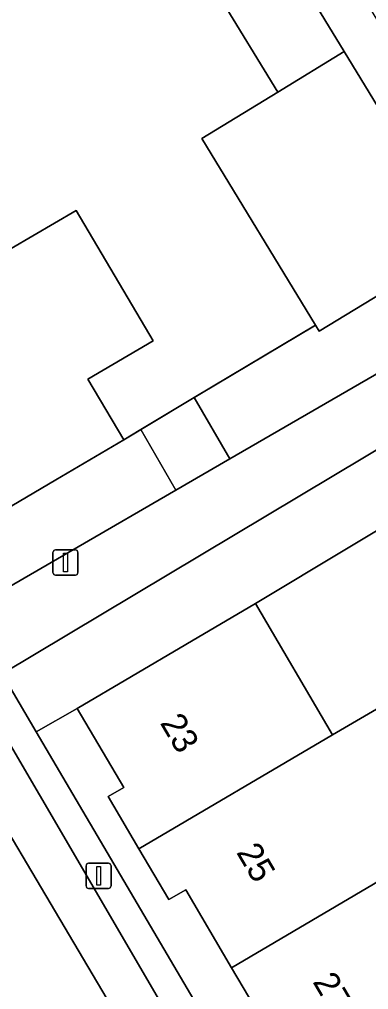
# Model space of a CAD drawing. Extents: x 159716 to 160783, y 383290 to 384031.
# Drawn here: x 160188.25 to 160202.09, y 383359.53 to 383397.98 of the extents above; entities that cross this region are included whole.
import ezdxf

# ---------------------------------------------------------------- set-up
doc = ezdxf.new("R2010")
doc.units = 0
for name, color, linetype in [('IMGEO_Erf', 7, 'Continuous'), ('IMGEO_Groenvoorziening', 7, 'Continuous'), ('IMGEO_Lichtmast', 7, 'Continuous'), ('IMGEO_Muur', 7, 'Continuous'), ('IMGEO_Pand', 7, 'Continuous'), ('IMGEO_Pand_nummerreeks', 7, 'Continuous'), ('IMGEO_Parkeervlak_open', 7, 'Continuous'), ('IMGEO_Rijbaan_lokaal_open', 7, 'Continuous'), ('IMGEO_Voetpad_open', 7, 'Continuous')]:
    doc.layers.add(name, color=color, linetype=linetype)

msp = doc.modelspace()

# ---------------------------------------------------------------- linework, layer by layer
at = {"layer": 'IMGEO_Erf'}
for points in [[(160181.914, 383399.101), (160184.914, 383394.006), (160187.924, 383388.895), (160190.508, 383390.403), (160193.555, 383385.244), (160190.972, 383383.719), (160192.386, 383381.318), (160193.063, 383381.722), (160195.185, 383382.99), (160199.992, 383385.86), (160195.482, 383393.257), (160198.495, 383395.094), (160196.187, 383398.879)], [(160227.095, 383381.23), (160221.425, 383377.618), (160221.195, 383377.966), (160215.218, 383374.346), (160210.282, 383382.434), (160208.629, 383381.443), (160197.607, 383374.829), (160200.666, 383369.63), (160202.72, 383370.829), (160204.837, 383372.065), (160205.907, 383370.232), (160204.528, 383369.427), (160206.435, 383366.161), (160206.78, 383366.365), (160208.731, 383363.025), (160210.088, 383363.872), (160211.199, 383362.093), (160206.673, 383359.423)], [(160198.463, 383357.343), (160196.666, 383360.397), (160194.844, 383363.493), (160194.175, 383363.099), (160192.992, 383365.109), (160191.774, 383367.179), (160192.387, 383367.54), (160190.544, 383370.673), (160188.923, 383369.749), (160213.993, 383327.146)]]:
    msp.add_lwpolyline(points, dxfattribs=at)
at = {"layer": 'IMGEO_Groenvoorziening'}
for points in [[(160200.487, 383401.152), (160200.376, 383401.334), (160198.823, 383400.487), (160201.131, 383396.702), (160205.789, 383389.062), (160207.21, 383386.705), (160208.76, 383387.602)], [(160207.21, 383386.705), (160205.789, 383389.062), (160200.14, 383385.618), (160199.992, 383385.86), (160195.185, 383382.99), (160196.592, 383380.559)], [(160208.629, 383381.443), (160207.249, 383383.817), (160187.571, 383372.047), (160188.923, 383369.749), (160190.544, 383370.673), (160194.854, 383373.209), (160197.607, 383374.829)], [(160193.788, 383378.936), (160194.453, 383379.321), (160193.063, 383381.722), (160192.386, 383381.318), (160189.694, 383379.733), (160185.385, 383377.195), (160184.751, 383376.839), (160186.126, 383374.501)]]:
    msp.add_lwpolyline(points, close=True, dxfattribs=at)
at = {"layer": 'IMGEO_Lichtmast'}
for p, q in [((160189.685, 383376.956), (160190.475, 383376.956)), ((160190.475, 383376.956), (160189.685, 383376.956)), ((160189.585, 383376.056), (160189.585, 383376.856)), ((160189.585, 383376.856), (160189.585, 383376.056)), ((160190.575, 383376.856), (160190.575, 383376.056)), ((160190.575, 383376.056), (160190.575, 383376.856)), ((160190.475, 383375.956), (160189.685, 383375.956)), ((160189.685, 383375.956), (160190.475, 383375.956)), ((160190.896, 383363.641), (160190.896, 383364.441)), ((160190.896, 383364.441), (160190.896, 383363.641)), ((160190.996, 383364.541), (160191.786, 383364.541)), ((160191.786, 383364.541), (160190.996, 383364.541)), ((160191.886, 383364.441), (160191.886, 383363.641)), ((160191.886, 383363.641), (160191.886, 383364.441)), ((160191.786, 383363.541), (160190.996, 383363.541)), ((160190.996, 383363.541), (160191.786, 383363.541))]:
    msp.add_line(p, q, dxfattribs=at)
for points in [[(160190.005, 383376.831), (160190.155, 383376.831), (160190.155, 383376.081), (160190.005, 383376.081), (160190.005, 383376.831)], [(160191.316, 383364.416), (160191.466, 383364.416), (160191.466, 383363.666), (160191.316, 383363.666), (160191.316, 383364.416)]]:
    msp.add_lwpolyline(points, dxfattribs=at)
for centre, start, end in [((160189.685, 383376.856), 90, 180), ((160189.685, 383376.856), 90, 180), ((160190.475, 383376.856), 0, 90), ((160190.475, 383376.856), 360, 90), ((160189.685, 383376.056), 180, 270), ((160189.685, 383376.056), 180, 270), ((160190.475, 383376.056), 270, 0), ((160190.475, 383376.056), 270, 0), ((160190.996, 383364.441), 90, 180), ((160190.996, 383364.441), 90, 180), ((160191.786, 383364.441), 0, 90), ((160191.786, 383364.441), 360, 90), ((160190.996, 383363.641), 180, 270), ((160190.996, 383363.641), 180, 270), ((160191.786, 383363.641), 270, 0), ((160191.786, 383363.641), 270, 0)]:
    msp.add_arc(centre, 0.1, start, end, dxfattribs=at)
at = {"layer": 'IMGEO_Muur'}
for points in [[(160194.79, 383382.754), (160199.955, 383385.838)], [(160192.386, 383381.318), (160194.79, 383382.754)]]:
    msp.add_lwpolyline(points, dxfattribs=at)
at = {"layer": 'IMGEO_Pand'}
for points in [[(160198.823, 383400.487), (160196.187, 383398.879), (160198.495, 383395.094), (160201.131, 383396.702)], [(160201.131, 383396.702), (160198.495, 383395.094), (160195.482, 383393.257), (160199.992, 383385.86), (160200.14, 383385.618), (160205.789, 383389.062)], [(160187.924, 383388.895), (160180.303, 383384.395), (160181.49, 383382.38), (160182.115, 383382.748), (160185.385, 383377.195), (160189.694, 383379.733), (160192.386, 383381.318), (160190.972, 383383.719), (160193.555, 383385.244), (160190.508, 383390.403)], [(160200.666, 383369.63), (160197.607, 383374.829), (160194.854, 383373.209), (160190.544, 383370.673), (160192.387, 383367.54), (160191.774, 383367.179), (160192.992, 383365.109)], [(160196.666, 383360.397), (160206.435, 383366.161), (160204.528, 383369.427), (160205.907, 383370.232), (160204.837, 383372.065), (160202.72, 383370.829), (160200.666, 383369.63), (160192.992, 383365.109), (160194.175, 383363.099), (160194.844, 383363.493)], [(160196.666, 383360.397), (160198.463, 383357.343), (160197.845, 383356.979), (160199.052, 383354.927), (160206.673, 383359.423), (160211.199, 383362.093), (160210.088, 383363.872), (160208.731, 383363.025), (160206.78, 383366.365), (160206.435, 383366.161)]]:
    msp.add_lwpolyline(points, close=True, dxfattribs=at)
at = {"layer": 'IMGEO_Parkeervlak_open'}
msp.add_lwpolyline([(160200.924, 383346.903), (160189.051, 383367.258), (160185.683, 383372.991), (160184.085, 383372.06), (160200.823, 383343.792)], dxfattribs=at)
at = {"layer": 'IMGEO_Rijbaan_lokaal_open'}
msp.add_lwpolyline([(160184.085, 383372.06), (160182.74, 383374.363), (160169.109, 383397.517), (160169.006, 383397.691), (160165.976, 383395.906), (160166.305, 383395.343), (160177.078, 383376.916), (160177.537, 383376.126), (160180.532, 383370.974), (160181.334, 383369.594), (160181.878, 383368.671), (160197.651, 383341.936), (160200.823, 383343.792)], close=True, dxfattribs=at)
at = {"layer": 'IMGEO_Voetpad_open'}
for points in [[(160211.961, 383386.555), (160219.484, 383390.925), (160220.254, 383391.373), (160226.605, 383394.998), (160225.284, 383397.372), (160210.579, 383388.728), (160208.76, 383387.602), (160207.21, 383386.705), (160196.592, 383380.559), (160194.453, 383379.321), (160193.788, 383378.936), (160186.126, 383374.501), (160187.571, 383372.047), (160207.249, 383383.817), (160208.51, 383384.55), (160208.865, 383384.756)], [(160195.185, 383382.99), (160193.063, 383381.722), (160194.453, 383379.321), (160196.592, 383380.559)]]:
    msp.add_lwpolyline(points, close=True, dxfattribs=at)
for points in [[(160172.212, 383395.883), (160177.962, 383386.112), (160182.336, 383378.779), (160182.688, 383378.976), (160184.645, 383375.724), (160184.257, 383375.524), (160184.381, 383375.3), (160182.74, 383374.363), (160184.085, 383372.06), (160185.683, 383372.991), (160189.051, 383367.258), (160200.924, 383346.903)], [(160215.425, 383318.797), (160216.414, 383317.124), (160219.193, 383318.286), (160215.167, 383325.168), (160213.993, 383327.146), (160188.923, 383369.749), (160187.571, 383372.047), (160186.126, 383374.501), (160184.751, 383376.839)]]:
    msp.add_lwpolyline(points, dxfattribs=at)

# ---------------------------------------------------------------- texts
at = {"layer": 'IMGEO_Pand_nummerreeks'}
for s, p in [('23', (160193.807, 383370.102)), ('25', (160196.832, 383364.974)), ('27', (160199.857, 383359.846))]:
    msp.add_text(s, height=1, rotation=300.5374, dxfattribs=at).set_placement(p)

doc.saveas('drawing.dxf')
